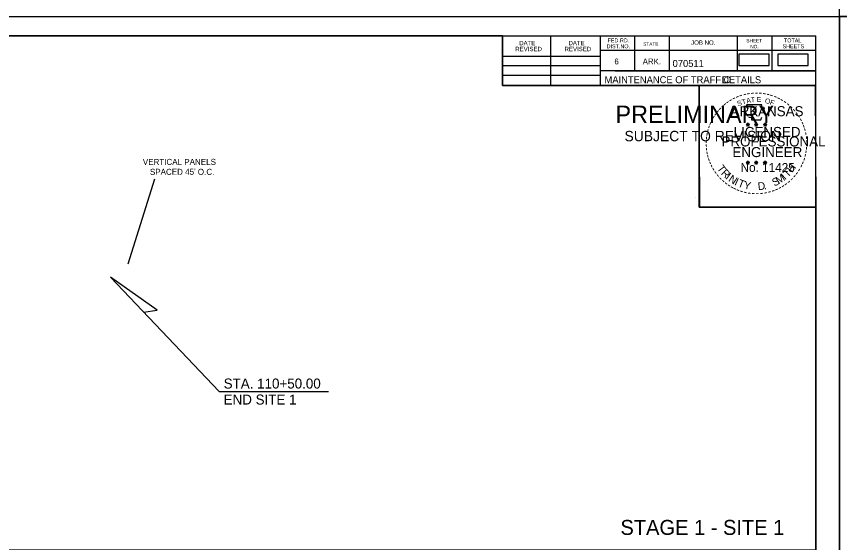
# Model space of a CAD drawing. Extents: x 1398460 to 1408037, y 380768 to 383968.
# Drawn here: x 1401509 to 1402332, y 382375 to 382901 of the extents above; entities that cross this region are included whole.
import ezdxf

# ---------------------------------------------------------------- set-up
doc = ezdxf.new("R2010")
doc.units = 0
for name, color, linetype in [('Default', 7, 'Continuous'), ('MOT STAGE ALL', 7, 'Continuous'), ('R_Border', 7, 'Continuous'), ('R_Border PE', 7, 'Continuous'), ('R_Border Prem', 7, 'Continuous'), ('R_Dimension', 7, 'Continuous'), ('R_MOT', 7, 'Continuous'), ('R_No Plot', 7, 'Continuous')]:
    doc.layers.add(name, color=color, linetype=linetype)

msp = doc.modelspace()

# ---------------------------------------------------------------- linework, layer by layer
at = {"layer": 'Default'}
for p, q in [((1401603.27, 382640.31), (1401712.07, 382526.14)), ((1401712.07, 382526.14), (1401821.35, 382526.14))]:
    msp.add_line(p, q, dxfattribs=at)
msp.add_lwpolyline([(1401636.5, 382605.44), (1401650.12, 382607.31), (1401603.27, 382640.31)], dxfattribs=at)
at = {"layer": 'R_Border'}
for p, q in [((1400727.57, 382881.42), (1402308.47, 382881.42)), ((1401995.27, 382832.02), (1401995.27, 382881.42)), ((1402043.67, 382832.02), (1402043.67, 382881.42)), ((1402092.97, 382881.42), (1402092.97, 382832.02)), ((1402127.17, 382881.42), (1402127.17, 382846.72)), ((1402161.87, 382881.42), (1402161.87, 382846.72)), ((1402229.77, 382881.42), (1402229.77, 382846.72)), ((1402264.47, 382881.42), (1402264.47, 382846.72)), ((1402308.47, 381854.12), (1402308.47, 382881.42)), ((1402308.47, 382866.72), (1402092.97, 382866.72)), ((1402308.47, 382866.82), (1402308.47, 382866.82)), ((1401995.27, 382861.32), (1402092.97, 382861.32)), ((1401995.27, 382852.02), (1402092.97, 382852.02)), ((1401995.27, 382842.32), (1402092.97, 382842.32)), ((1402308.47, 382846.72), (1402092.97, 382846.72)), ((1402107.77, 382846.72), (1402308.47, 382846.72)), ((1402308.47, 382832.02), (1401995.27, 382832.02))]:
    msp.add_line(p, q, dxfattribs=at)
at = {"layer": 'R_Border PE'}
for p, q in [((1402238.89, 382793.29), (1402240.64, 382792.74)), ((1402238.89, 382793.29), (1402240.16, 382793.07)), ((1402238.89, 382793.29), (1402240.08, 382792.68)), ((1402239.56, 382791.25), (1402240.64, 382792.74)), ((1402239.56, 382791.25), (1402240.19, 382792.47)), ((1402239.56, 382791.25), (1402240.63, 382792.34)), ((1402240.64, 382794.56), (1402240.43, 382793.3)), ((1402241.7, 382791.25), (1402240.63, 382792.32)), ((1402240.64, 382792.74), (1402240.64, 382794.56)), ((1402240.64, 382794.56), (1402240.88, 382793.31)), ((1402242.37, 382793.29), (1402240.64, 382792.74)), ((1402241.7, 382791.25), (1402240.64, 382792.74)), ((1402242.37, 382793.29), (1402240.94, 382793.05)), ((1402241.7, 382791.25), (1402241.02, 382792.71)), ((1402242.37, 382793.29), (1402241.35, 382792.78)), ((1402247.24, 382793.29), (1402248.99, 382792.74)), ((1402247.24, 382793.29), (1402248.51, 382793.07)), ((1402247.24, 382793.29), (1402248.43, 382792.68)), ((1402247.91, 382791.25), (1402248.99, 382792.74)), ((1402247.91, 382791.25), (1402248.54, 382792.47)), ((1402247.91, 382791.25), (1402248.98, 382792.34)), ((1402248.99, 382794.56), (1402248.78, 382793.3)), ((1402250.05, 382791.25), (1402248.98, 382792.32)), ((1402248.99, 382792.74), (1402248.99, 382794.56)), ((1402248.99, 382794.56), (1402249.23, 382793.31)), ((1402250.72, 382793.29), (1402248.99, 382792.74)), ((1402250.05, 382791.25), (1402248.99, 382792.74)), ((1402250.72, 382793.29), (1402249.29, 382793.05)), ((1402250.05, 382791.25), (1402249.37, 382792.71)), ((1402250.72, 382793.29), (1402249.7, 382792.78)), ((1402256.06, 382793.23), (1402257.81, 382792.68)), ((1402256.06, 382793.23), (1402257.33, 382793.01)), ((1402256.06, 382793.23), (1402257.25, 382792.62)), ((1402256.73, 382791.19), (1402257.81, 382792.68)), ((1402256.73, 382791.19), (1402257.36, 382792.41)), ((1402256.73, 382791.19), (1402257.8, 382792.28)), ((1402257.81, 382794.5), (1402257.6, 382793.24)), ((1402258.87, 382791.19), (1402257.8, 382792.26)), ((1402257.81, 382792.68), (1402257.81, 382794.5)), ((1402257.81, 382794.5), (1402258.05, 382793.25)), ((1402259.54, 382793.23), (1402257.81, 382792.68)), ((1402258.87, 382791.19), (1402257.81, 382792.68)), ((1402259.54, 382793.23), (1402258.11, 382792.99)), ((1402258.87, 382791.19), (1402258.19, 382792.65)), ((1402259.54, 382793.23), (1402258.52, 382792.72)), ((1402238.87, 382755.43), (1402240.62, 382754.87)), ((1402238.87, 382755.43), (1402240.14, 382755.2)), ((1402238.87, 382755.43), (1402240.06, 382754.82)), ((1402239.54, 382753.39), (1402240.62, 382754.87)), ((1402239.54, 382753.39), (1402240.17, 382754.61)), ((1402239.54, 382753.39), (1402240.61, 382754.47)), ((1402240.62, 382756.7), (1402240.41, 382755.44)), ((1402241.68, 382753.39), (1402240.61, 382754.46)), ((1402240.62, 382754.87), (1402240.62, 382756.7)), ((1402240.62, 382756.7), (1402240.86, 382755.45)), ((1402242.35, 382755.43), (1402240.62, 382754.87)), ((1402241.68, 382753.39), (1402240.62, 382754.87)), ((1402242.35, 382755.43), (1402240.92, 382755.18)), ((1402241.68, 382753.39), (1402241, 382754.84)), ((1402242.35, 382755.43), (1402241.33, 382754.92)), ((1402247.22, 382755.43), (1402248.96, 382754.87)), ((1402247.22, 382755.43), (1402248.48, 382755.2)), ((1402247.22, 382755.43), (1402248.4, 382754.82)), ((1402247.88, 382753.39), (1402248.96, 382754.87)), ((1402247.88, 382753.39), (1402248.51, 382754.61)), ((1402247.88, 382753.39), (1402248.95, 382754.47)), ((1402248.96, 382756.7), (1402248.76, 382755.44)), ((1402250.03, 382753.39), (1402248.95, 382754.46)), ((1402248.96, 382754.87), (1402248.96, 382756.7)), ((1402248.96, 382756.7), (1402249.21, 382755.45)), ((1402250.7, 382755.43), (1402248.96, 382754.87)), ((1402250.03, 382753.39), (1402248.96, 382754.87)), ((1402250.7, 382755.43), (1402249.27, 382755.18)), ((1402250.03, 382753.39), (1402249.34, 382754.84)), ((1402250.7, 382755.43), (1402249.68, 382754.92)), ((1402256.05, 382755.38), (1402257.8, 382754.82)), ((1402256.05, 382755.38), (1402257.32, 382755.15)), ((1402256.05, 382755.38), (1402257.24, 382754.77)), ((1402256.72, 382753.34), (1402257.8, 382754.82)), ((1402256.72, 382753.34), (1402257.35, 382754.56)), ((1402256.72, 382753.34), (1402257.79, 382754.42)), ((1402257.8, 382756.65), (1402257.59, 382755.39)), ((1402258.86, 382753.34), (1402257.79, 382754.41)), ((1402257.8, 382754.82), (1402257.8, 382756.65)), ((1402257.8, 382756.65), (1402258.04, 382755.4)), ((1402259.53, 382755.38), (1402257.8, 382754.82)), ((1402258.86, 382753.34), (1402257.8, 382754.82)), ((1402259.53, 382755.38), (1402258.1, 382755.13)), ((1402258.86, 382753.34), (1402258.18, 382754.79)), ((1402259.53, 382755.38), (1402258.51, 382754.87))]:
    msp.add_line(p, q, dxfattribs=at)
for points in [[(1402239.1, 382812.68), (1402240.44, 382808.55)], [(1402256.65, 382808.07), (1402257.36, 382809.49), (1402253.94, 382809.37), (1402254.68, 382812.68), (1402239.1, 382812.68)], [(1402241.56, 382800.57), (1402241.56, 382800.13), (1402244.37, 382800.04), (1402244.1, 382797.67), (1402253.45, 382797.67), (1402254.46, 382800.35)], [(1402240.64, 382794.56), (1402241.7, 382791.25), (1402238.89, 382793.29), (1402242.37, 382793.29), (1402239.56, 382791.25), (1402240.64, 382794.56)], [(1402248.99, 382794.56), (1402250.05, 382791.25), (1402247.24, 382793.29), (1402250.72, 382793.29), (1402247.91, 382791.25), (1402248.99, 382794.56)], [(1402257.81, 382794.5), (1402258.87, 382791.19), (1402256.06, 382793.23), (1402259.54, 382793.23), (1402256.73, 382791.19), (1402257.81, 382794.5)], [(1402240.62, 382756.7), (1402241.68, 382753.39), (1402238.87, 382755.43), (1402242.35, 382755.43), (1402239.54, 382753.39), (1402240.62, 382756.7)], [(1402248.96, 382756.7), (1402250.03, 382753.39), (1402247.22, 382755.43), (1402250.7, 382755.43), (1402247.88, 382753.39), (1402248.96, 382756.7)], [(1402257.8, 382756.65), (1402258.86, 382753.34), (1402256.05, 382755.38), (1402259.53, 382755.38), (1402256.72, 382753.34), (1402257.8, 382756.65)]]:
    msp.add_lwpolyline(points, dxfattribs=at)
for centre, radius in [((1402240.63, 382792.73), 0.861), ((1402240.63, 382792.73), 0.723), ((1402240.63, 382792.73), 0.579), ((1402240.63, 382792.73), 0.495), ((1402240.63, 382792.73), 0.374), ((1402240.63, 382792.73), 0.248), ((1402240.63, 382792.73), 0.148), ((1402248.98, 382792.73), 0.861), ((1402248.98, 382792.73), 0.723), ((1402248.98, 382792.73), 0.579), ((1402248.98, 382792.73), 0.495), ((1402248.98, 382792.73), 0.374), ((1402248.98, 382792.73), 0.248), ((1402248.98, 382792.73), 0.148), ((1402257.8, 382792.67), 0.861), ((1402257.8, 382792.67), 0.723), ((1402257.8, 382792.67), 0.579), ((1402257.8, 382792.67), 0.495), ((1402257.8, 382792.67), 0.374), ((1402257.8, 382792.67), 0.248), ((1402257.8, 382792.67), 0.148), ((1402240.61, 382754.87), 0.861), ((1402240.61, 382754.87), 0.723), ((1402240.61, 382754.87), 0.579), ((1402240.61, 382754.87), 0.495), ((1402240.61, 382754.87), 0.374), ((1402240.61, 382754.87), 0.248), ((1402240.61, 382754.87), 0.148), ((1402248.96, 382754.87), 0.861), ((1402248.96, 382754.87), 0.723), ((1402248.96, 382754.87), 0.579), ((1402248.96, 382754.87), 0.495), ((1402248.96, 382754.87), 0.374), ((1402248.96, 382754.87), 0.248), ((1402248.96, 382754.87), 0.148), ((1402257.79, 382754.82), 0.861), ((1402257.79, 382754.82), 0.723), ((1402257.79, 382754.82), 0.579), ((1402257.79, 382754.82), 0.495), ((1402257.79, 382754.82), 0.374), ((1402257.79, 382754.82), 0.248), ((1402257.79, 382754.82), 0.148)]:
    msp.add_circle(centre, radius, dxfattribs=at)
at = {"layer": 'R_Dimension'}
for points in [[(1402231.64, 382851.73), (1402261.91, 382851.73), (1402261.91, 382863.28), (1402231.64, 382863.28)], [(1402270.66, 382851.79), (1402300.93, 382851.79), (1402300.93, 382863.35), (1402270.66, 382863.35)]]:
    msp.add_lwpolyline(points, close=True, dxfattribs=at)
at = {"layer": 'R_MOT'}
msp.add_line((1401621.11, 382653.73), (1401647.73, 382738.57), dxfattribs=at)
at = {"layer": 'R_No Plot'}
msp.add_line((1402188.64, 382719.74), (1402188.64, 382719.74), dxfattribs=at)
for points in [[(1402332.23, 383967.58), (1403998.93, 383967.58), (1403998.93, 382900.89), (1402332.23, 382900.89)], [(1400665.53, 382900.89), (1402332.23, 382900.89), (1402332.23, 381834.2), (1400665.53, 381834.2)], [(1402332.23, 382900.89), (1403998.93, 382900.89), (1403998.93, 381834.2), (1402332.23, 381834.2)], [(1400727.57, 382881.42), (1400727.57, 381854.12), (1402308.47, 381854.12), (1402308.47, 382710.36), (1402191.82, 382710.36), (1402191.82, 382832.02), (1401995.27, 382832.02), (1401995.27, 382881.42)], [(1400727.57, 382881.42), (1400727.57, 382367.77), (1402308.47, 382367.77), (1402308.47, 382710.36), (1402191.82, 382710.36), (1402191.82, 382832.02), (1401995.27, 382832.02), (1401995.27, 382881.42)], [(1401897.17, 382881.42), (1401995.27, 382881.42), (1401995.27, 382832.02), (1402075.83, 382832.02), (1402191.82, 382832.02), (1402191.82, 382710.36), (1402308.47, 382710.36), (1402308.47, 381854.12), (1400727.57, 381854.12), (1400727.57, 382881.42)], [(1402191.82, 382832.02), (1402307.86, 382832.02), (1402308.47, 382710.36), (1402192.43, 382710.36)]]:
    msp.add_lwpolyline(points, close=True, dxfattribs=at)

# ---------------------------------------------------------------- texts
at = {"layer": 'MOT STAGE ALL'}
for s, p in [('VERTICAL PANELS', (1401635.71, 382752.59)), ("SPACED 45' O.C. ", (1401642.8, 382742.63))]:
    msp.add_text(s, height=6.0001, rotation=0, dxfattribs=at).set_placement(p)
at = {"layer": 'R_Border'}
for s, height, p in [('DATE', 4.396, (1402011.96, 382872.1)), ('DATE', 4.396, (1402061.26, 382872.1)), ('DIST.NO.', 3.91, (1402099.37, 382869.12)), ('FED.RD.', 3.91, (1402100.37, 382875.02)), ('STATE', 3.42, (1402135.97, 382871.62)), ('JOB NO.', 4.396, (1402183.87, 382872.62)), ('SHEET', 3.42, (1402239.07, 382875.02)), ('SHEETS', 3.91, (1402275.27, 382869.12)), ('TOTAL', 3.91, (1402276.67, 382875.02)), ('REVISED', 4.396, (1402008.06, 382866.2)), ('REVISED', 4.396, (1402057.36, 382866.2)), ('NO.', 3.42, (1402242.97, 382869.12)), ('6', 5.86, (1402107.17, 382853.02)), ('ARK.', 5.861, (1402135.47, 382853.02)), ('070511', 7, (1402165.35, 382850.42)), ('MAINTENANCE OF TRAFFIC', 7, (1402097.28, 382834.17)), (' DETAILS', 7, (1402212.28, 382834.17)), ('STAGE 1 - SITE 1 ', 15, (1402113.19, 382382.79))]:
    msp.add_text(s, height=height, dxfattribs=at).set_placement(p)
at = {"layer": 'R_Border PE'}
for s, height, rotation, p in [('-', 8, 13.63015, (1402236.59, 382819.52)), ('-', 8, 10.21935, (1402239.98, 382820.33)), ('-', 8, 5.89682, (1402243.62, 382820.88)), ('-', 8, 0.18623, (1402247.48, 382821.24)), ('-', 8, 357.74304, (1402251.1, 382821.18)), ('-', 8, 352.16172, (1402254.82, 382820.9)), ('-', 8, 347.20489, (1402258.41, 382820.33)), ('-', 8, 36.23174, (1402220.63, 382811.56)), ('-', 8, 34.06357, (1402223.52, 382813.54)), ('-', 8, 28.79182, (1402226.5, 382815.39)), ('-', 8, 24.30721, (1402229.67, 382816.97)), ('S', 5, 21.59401, (1402230.87, 382811.07)), ('-', 8, 19.17608, (1402232.84, 382818.32)), ('T', 5, 16.4036, (1402235.44, 382812.73)), ('A', 5, 11.21318, (1402239.57, 382813.98)), ('T', 5, 6.02276, (1402243.82, 382814.81)), ('E', 5, 0.83234, (1402249.34, 382815.36)), ('O', 5, 350.4515, (1402257.36, 382814.31)), ('F', 5, 340.07066, (1402262.13, 382813.17)), ('-', 8, 342.3362, (1402261.59, 382819.55)), ('-', 8, 337.85509, (1402265.26, 382818.44)), ('-', 8, 334.12109, (1402268.42, 382817.08)), ('-', 8, 329.64089, (1402271.31, 382815.67)), ('-', 8, 325.86266, (1402274.53, 382813.86)), ('-', 8, 50.61417, (1402211.83, 382802.77)), ('-', 8, 48.42305, (1402213.84, 382805.2)), ('-', 8, 42.96224, (1402216.08, 382807.59)), ('-', 8, 38.95066, (1402218.25, 382809.67)), ('-', 8, 320.52971, (1402277.58, 382811.73)), ('-', 8, 315.57859, (1402280.57, 382809.29)), ('-', 8, 309.87973, (1402283.42, 382806.54)), ('-', 8, 58.07063, (1402208.14, 382797.3)), ('-', 8, 54.23247, (1402209.76, 382799.93)), ('-', 8, 306.65218, (1402286.04, 382803.53)), ('-', 7, 303.67529, (1402288.47, 382800.69)), ('-', 8, 299.66835, (1402290.07, 382797.66)), ('-', 8, 72.39447, (1402204.18, 382788.02)), ('-', 8, 67.77427, (1402205.28, 382791.17)), ('-', 8, 62.87135, (1402206.57, 382794.23)), ('-', 8, 294.66279, (1402291.69, 382794.6)), ('-', 8, 290.57283, (1402292.97, 382791.71)), ('-', 8, 81.20126, (1402202.54, 382780.89)), ('-', 8, 75.46096, (1402203.2, 382784.45)), ('-', 8, 285.12326, (1402294.14, 382788.81)), ('-', 8, 280.54934, (1402295.14, 382785.1)), ('-', 8, 89.06224, (1402202.03, 382773.93)), ('-', 8, 85.18634, (1402202.16, 382777.43)), ('-', 8, 276.59616, (1402295.95, 382781.26)), ('-', 8, 274.33011, (1402296.25, 382777.65)), ('-', 8, 269.94067, (1402296.42, 382774.49)), ('-', 8, 94.19588, (1402202.21, 382770.3)), ('-', 8, 98.94793, (1402202.57, 382766.97)), ('-', 8, 101.71495, (1402203.24, 382763.3)), ('-', 8, 260.99529, (1402295.97, 382767.89)), ('-', 8, 263.5172, (1402296.33, 382771.16)), ('-', 8, 105.45785, (1402204.05, 382760.33)), ('-', 8, 109.08742, (1402205.13, 382757.17)), ('-', 8, 252.86809, (1402294.52, 382760.9)), ('-', 8, 255.7626, (1402295.42, 382764.5)), ('-', 8, 114.06432, (1402206.4, 382754.19)), ('-', 8, 115.72885, (1402207.92, 382751.1)), ('-', 8, 120.44712, (1402209.71, 382748.17)), ('T', 7.7, 306.04056, (1402209.41, 382749.06)), ('H', 7.7, 54.60883, (1402285.01, 382744.24)), ('-', 8, 244.61971, (1402292.09, 382754.39)), ('-', 8, 247.88866, (1402293.4, 382757.54)), ('-', 8, 125.89344, (1402211.72, 382745.37)), ('-', 8, 130.71812, (1402214.03, 382742.61)), ('R', 7.7, 314.00497, (1402213.23, 382743.83)), ('I', 7.7, 321.96938, (1402217.73, 382739.17)), ('N', 7.7, 326.50021, (1402220.56, 382736.81)), ('M', 7.7, 32.65632, (1402271.34, 382732.9)), ('I', 7.7, 42.11359, (1402277.76, 382737.14)), ('T', 7.7, 46.64442, (1402280.57, 382739.53)), ('-', 8, 231.25377, (1402285.96, 382744.54)), ('-', 8, 233.84524, (1402288.11, 382747.37)), ('-', 8, 239.07125, (1402290.12, 382750.63)), ('-', 8, 134.22381, (1402216.62, 382739.88)), ('-', 8, 138.93382, (1402219.24, 382737.56)), ('-', 8, 144.64634, (1402222.02, 382735.53)), ('-', 8, 148.08978, (1402224.83, 382733.68)), ('I', 7.7, 335.36034, (1402226.61, 382732.88)), ('T', 7.7, 339.89117, (1402229.91, 382731.24)), ('Y', 7.7, 347.85558, (1402236, 382729.01)), ('D', 7.7, 6.39691, (1402250.92, 382727.22)), ('S', 7.7, 26.9312, (1402267.14, 382730.87)), ('-', 8, 215.73633, (1402278.21, 382736.81)), ('-', 8, 221.08509, (1402280.96, 382739.17)), ('-', 8, 225.76533, (1402283.57, 382741.72)), ('-', 8, 151.57039, (1402227.72, 382732.05)), ('-', 8, 154.60019, (1402230.33, 382730.82)), ('-', 8, 158.56121, (1402233.45, 382729.55)), ('-', 8, 162.79826, (1402236.89, 382728.48)), ('-', 8, 167.55551, (1402240.46, 382727.66)), ('-', 8, 173.11546, (1402244.32, 382727.11)), ('-', 8, 185.81666, (1402255.83, 382727.32)), ('-', 8, 191.28576, (1402259.51, 382727.98)), ('.', 7.7, 13.76417, (1402256.88, 382727.86)), ('-', 8, 195.47429, (1402263.15, 382728.98)), ('-', 8, 200.71842, (1402266.54, 382730.19)), ('-', 8, 204.25161, (1402269.63, 382731.55)), ('-', 8, 207.35684, (1402272.75, 382733.15)), ('-', 8, 212.24909, (1402275.54, 382734.88)), ('-', 8, 176.51827, (1402248.06, 382726.85)), ('-', 8, 181.59176, (1402251.78, 382726.94))]:
    msp.add_text(s, height=height, rotation=rotation, dxfattribs=at).set_placement(p)
for s, height, p in [('ARKANSAS', 10, (1402223.36, 382801.24)), ('LICENSED', 10, (1402226.35, 382780.5)), ('DWB', 0.05, (1402240.57, 382792.71)), ('DWB', 0.05, (1402248.92, 382792.71)), ('DWB', 0.05, (1402257.74, 382792.66)), ('PROFESSIONAL', 10, (1402214.23, 382770.98)), ('ENGINEER', 10, (1402225.17, 382760.35)), ('No. 11425', 8.785, (1402233.3, 382745.6)), ('DWB', 0.05, (1402240.55, 382754.85)), ('DWB', 0.05, (1402248.9, 382754.85)), ('DWB', 0.05, (1402257.73, 382754.8))]:
    msp.add_text(s, height=height, dxfattribs=at).set_placement(p)
at = {"layer": 'R_Border Prem'}
for s, height, p in [('PRELIMINARY', 17.5, (1402108.22, 382794.33)), ('DWB', 0.05, (1402111.96, 382803.58)), ('SUBJECT TO REVISION', 10.3756, (1402117.27, 382776.19))]:
    msp.add_text(s, height=height, dxfattribs=at).set_placement(p)
at = {"layer": 'R_Dimension'}
for s, p in [('STA. 110+50.00', (1401716.55, 382529.06)), ('END SITE 1', (1401716.55, 382513.06))]:
    msp.add_text(s, height=10, dxfattribs=at).set_placement(p)

doc.saveas('drawing.dxf')
